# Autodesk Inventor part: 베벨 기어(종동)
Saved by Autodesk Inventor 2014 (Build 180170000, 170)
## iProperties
Created: 2026-05
Part Number: 베벨 기어(종동)
Material: 강철, 합금
Document SubType Name: Modeling
Designer: dg
Density: 7.85 g/cm^3
Appearance: 반연마
Mass: 563.834 g
Surface Area: 209.84 cm^2
Volume: 71.826 cm^3
Author: jhkim
Creation Date: 2026-04-23
Sending System: Autodesk Inventor 2027
Preprocessor: ST-DEVELOPER v20.1
Author: dg
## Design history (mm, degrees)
node "베벨 기어(종동)1"
body "Solid1"
node "기준1"
